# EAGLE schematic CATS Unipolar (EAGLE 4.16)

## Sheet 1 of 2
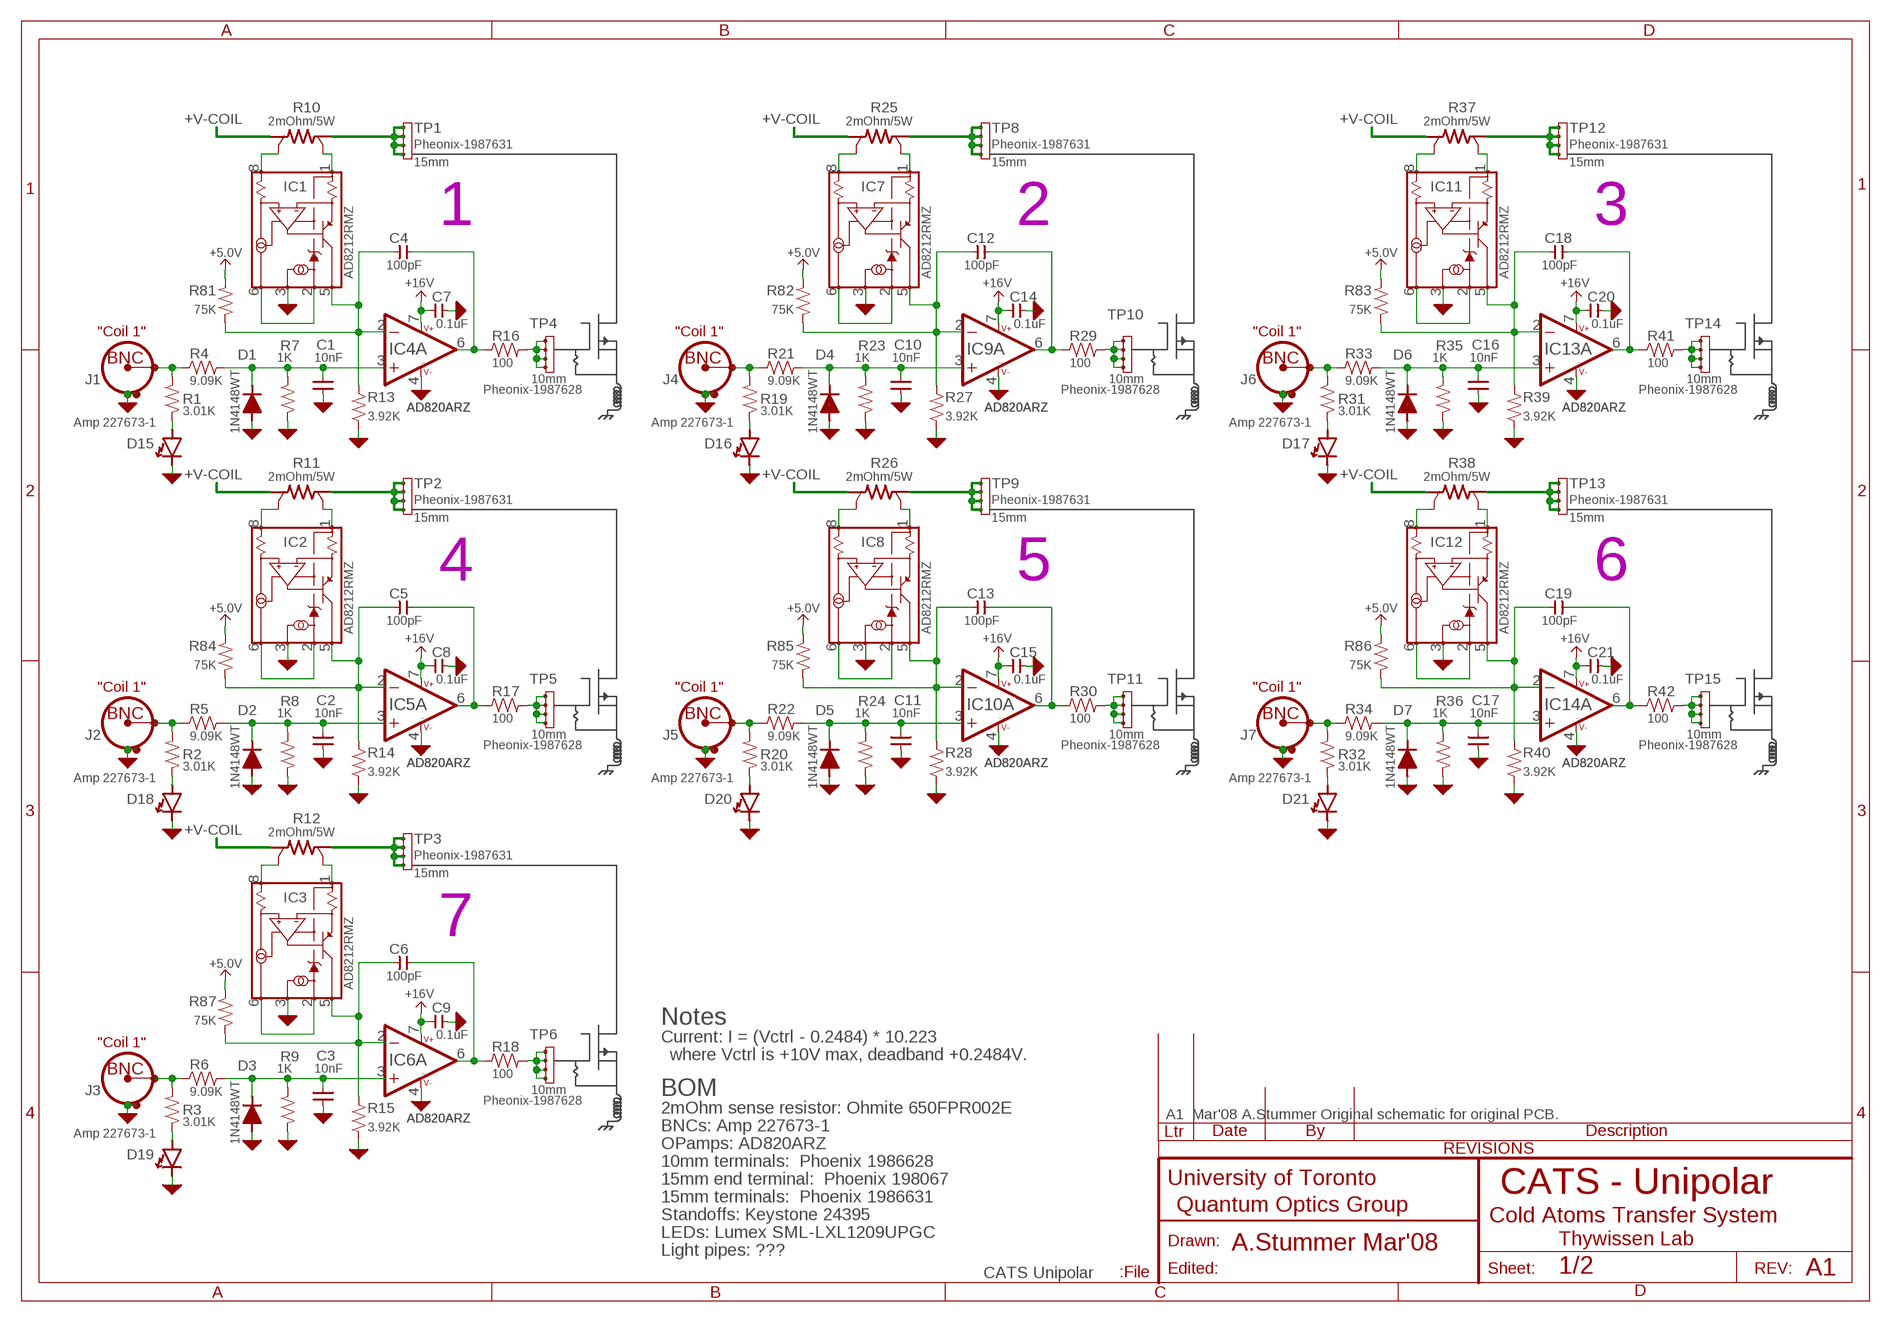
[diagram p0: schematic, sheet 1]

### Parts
C1  10nF  CAP-V-0805  [2012(0805)]
C2  10nF  CAP-V-0805  [2012(0805)]
C3  10nF  CAP-V-0805  [2012(0805)]
C4  100pF  CAP-H-0805  [2012(0805)]
C5  100pF  CAP-H-0805  [2012(0805)]
C6  100pF  CAP-H-0805  [2012(0805)]
C7  0.1uF  CAP-H-0805  [2012(0805)]
C8  0.1uF  CAP-H-0805  [2012(0805)]
C9  0.1uF  CAP-H-0805  [2012(0805)]
C10  10nF  CAP-V-0805  [2012(0805)]
C11  10nF  CAP-V-0805  [2012(0805)]
C12  100pF  CAP-H-0805  [2012(0805)]
C13  100pF  CAP-H-0805  [2012(0805)]
C14  0.1uF  CAP-H-0805  [2012(0805)]
C15  0.1uF  CAP-H-0805  [2012(0805)]
C16  10nF  CAP-V-0805  [2012(0805)]
C17  10nF  CAP-V-0805  [2012(0805)]
C18  100pF  CAP-H-0805  [2012(0805)]
C19  100pF  CAP-H-0805  [2012(0805)]
C20  0.1uF  CAP-H-0805  [2012(0805)]
C21  0.1uF  CAP-H-0805  [2012(0805)]
D1  1N4148WT  [SOD523]
D2  1N4148WT  [SOD523]
D3  1N4148WT  [SOD523]
D4  1N4148WT  [SOD523]
D5  1N4148WT  [SOD523]
D6  1N4148WT  [SOD523]
D7  1N4148WT  [SOD523]
D15  SML-LXL1209UPGC  LED-1209  [1209]
D16  SML-LXL1209UPGC  LED-1209  [1209]
D17  SML-LXL1209UPGC  LED-1209  [1209]
D18  SML-LXL1209UPGC  LED-1209  [1209]
D19  SML-LXL1209UPGC  LED-1209  [1209]
D20  SML-LXL1209UPGC  LED-1209  [1209]
D21  SML-LXL1209UPGC  LED-1209  [1209]
IC1  AD8212RMZ  AD8212(CURRENT_MONITOR)RMZ  [MSOP8]
IC2  AD8212RMZ  AD8212(CURRENT_MONITOR)RMZ  [MSOP8]
IC3  AD8212RMZ  AD8212(CURRENT_MONITOR)RMZ  [MSOP8]
IC4  AD820ARZ  OPAMP-SO8  [SOIC-8]
IC5  AD820ARZ  OPAMP-SO8  [SOIC-8]
IC6  AD820ARZ  OPAMP-SO8  [SOIC-8]
IC7  AD8212RMZ  AD8212(CURRENT_MONITOR)RMZ  [MSOP8]
IC8  AD8212RMZ  AD8212(CURRENT_MONITOR)RMZ  [MSOP8]
IC9  AD820ARZ  OPAMP-SO8  [SOIC-8]
IC10  AD820ARZ  OPAMP-SO8  [SOIC-8]
IC11  AD8212RMZ  AD8212(CURRENT_MONITOR)RMZ  [MSOP8]
IC12  AD8212RMZ  AD8212(CURRENT_MONITOR)RMZ  [MSOP8]
IC13  AD820ARZ  OPAMP-SO8  [SOIC-8]
IC14  AD820ARZ  OPAMP-SO8  [SOIC-8]
J1  Amp 227673-1  CONN-BNC-TYPE1VERT  [CONN-BNC-AMP-TYPE1VERT]
J2  Amp 227673-1  CONN-BNC-TYPE1VERT  [CONN-BNC-AMP-TYPE1VERT]
J3  Amp 227673-1  CONN-BNC-TYPE1VERT  [CONN-BNC-AMP-TYPE1VERT]
J4  Amp 227673-1  CONN-BNC-TYPE1VERT  [CONN-BNC-AMP-TYPE1VERT]
J5  Amp 227673-1  CONN-BNC-TYPE1VERT  [CONN-BNC-AMP-TYPE1VERT]
J6  Amp 227673-1  CONN-BNC-TYPE1VERT  [CONN-BNC-AMP-TYPE1VERT]
J7  Amp 227673-1  CONN-BNC-TYPE1VERT  [CONN-BNC-AMP-TYPE1VERT]
R1  3.01K  R-V-0805  [2012(0805)]
R2  3.01K  R-V-0805  [2012(0805)]
R3  3.01K  R-V-0805  [2012(0805)]
R4  9.09K  R-H-0805  [2012(0805)]
R5  9.09K  R-H-0805  [2012(0805)]
R6  9.09K  R-H-0805  [2012(0805)]
R7  1K  R-V-0805  [2012(0805)]
R8  1K  R-V-0805  [2012(0805)]
R9  1K  R-V-0805  [2012(0805)]
R10  2mOhm/5W  R-SENSE-OHMITE_650  [OHMITE_650]
R11  2mOhm/5W  R-SENSE-OHMITE_650  [OHMITE_650]
R12  2mOhm/5W  R-SENSE-OHMITE_650  [OHMITE_650]
R13  3.92K  R-V-0805  [2012(0805)]
R14  3.92K  R-V-0805  [2012(0805)]
R15  3.92K  R-V-0805  [2012(0805)]
R16  100  R-H-0805  [2012(0805)]
R17  100  R-H-0805  [2012(0805)]
R18  100  R-H-0805  [2012(0805)]
R19  3.01K  R-V-0805  [2012(0805)]
R20  3.01K  R-V-0805  [2012(0805)]
R21  9.09K  R-H-0805  [2012(0805)]
R22  9.09K  R-H-0805  [2012(0805)]
R23  1K  R-V-0805  [2012(0805)]
R24  1K  R-V-0805  [2012(0805)]
R25  2mOhm/5W  R-SENSE-OHMITE_650  [OHMITE_650]
R26  2mOhm/5W  R-SENSE-OHMITE_650  [OHMITE_650]
R27  3.92K  R-V-0805  [2012(0805)]
R28  3.92K  R-V-0805  [2012(0805)]
R29  100  R-H-0805  [2012(0805)]
R30  100  R-H-0805  [2012(0805)]
R31  3.01K  R-V-0805  [2012(0805)]
R32  3.01K  R-V-0805  [2012(0805)]
R33  9.09K  R-H-0805  [2012(0805)]
R34  9.09K  R-H-0805  [2012(0805)]
R35  1K  R-V-0805  [2012(0805)]
R36  1K  R-V-0805  [2012(0805)]
R37  2mOhm/5W  R-SENSE-OHMITE_650  [OHMITE_650]
R38  2mOhm/5W  R-SENSE-OHMITE_650  [OHMITE_650]
R39  3.92K  R-V-0805  [2012(0805)]
R40  3.92K  R-V-0805  [2012(0805)]
R41  100  R-H-0805  [2012(0805)]
R42  100  R-H-0805  [2012(0805)]
R81  75K  R-V-0805  [2012(0805)]
R82  75K  R-V-0805  [2012(0805)]
R83  75K  R-V-0805  [2012(0805)]
R84  75K  R-V-0805  [2012(0805)]
R85  75K  R-V-0805  [2012(0805)]
R86  75K  R-V-0805  [2012(0805)]
R87  75K  R-V-0805  [2012(0805)]
TP1  Pheonix-1987631  TP4-ZFKDS(10MM)  [PHEONIX_ZFKDS-10/15MM-TERMINAL-BLOCK]
TP2  Pheonix-1987631  TP4-ZFKDS(10MM)  [PHEONIX_ZFKDS-10/15MM-TERMINAL-BLOCK]
TP3  Pheonix-1987631  TP4-ZFKDS(10MM)  [PHEONIX_ZFKDS-10/15MM-TERMINAL-BLOCK]
TP4  Pheonix-1987628  TP4-ZFKDS(10MM)  [PHEONIX_ZFKDS-10/15MM-TERMINAL-BLOCK]
TP5  Pheonix-1987628  TP4-ZFKDS(10MM)  [PHEONIX_ZFKDS-10/15MM-TERMINAL-BLOCK]
TP6  Pheonix-1987628  TP4-ZFKDS(10MM)  [PHEONIX_ZFKDS-10/15MM-TERMINAL-BLOCK]
TP8  Pheonix-1987631  TP4-ZFKDS(10MM)  [PHEONIX_ZFKDS-10/15MM-TERMINAL-BLOCK]
TP9  Pheonix-1987631  TP4-ZFKDS(10MM)  [PHEONIX_ZFKDS-10/15MM-TERMINAL-BLOCK]
TP10  Pheonix-1987628  TP4-ZFKDS(10MM)  [PHEONIX_ZFKDS-10/15MM-TERMINAL-BLOCK]
TP11  Pheonix-1987628  TP4-ZFKDS(10MM)  [PHEONIX_ZFKDS-10/15MM-TERMINAL-BLOCK]
TP12  Pheonix-1987631  TP4-ZFKDS(10MM)  [PHEONIX_ZFKDS-10/15MM-TERMINAL-BLOCK]
TP13  Pheonix-1987631  TP4-ZFKDS(10MM)  [PHEONIX_ZFKDS-10/15MM-TERMINAL-BLOCK]
TP14  Pheonix-1987628  TP4-ZFKDS(10MM)  [PHEONIX_ZFKDS-10/15MM-TERMINAL-BLOCK]
TP15  Pheonix-1987628  TP4-ZFKDS(10MM)  [PHEONIX_ZFKDS-10/15MM-TERMINAL-BLOCK]

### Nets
+5.0V: R81.2 R82.2 R83.2 R84.2 R85.2 R86.2 R87.2 ; also sheet 2
+16V: C7.1 C8.1 C9.1 C14.1 C15.1 C20.1 C21.1 IC4.7(B:V+) IC5.7(B:V+) IC6.7(B:V+) IC9.7(B:V+) IC10.7(B:V+) IC13.7(B:V+) IC14.7(B:V+) ; also sheet 2
+V-COIL [Power]: R10.CURRENT1 R11.CURRENT1 R12.CURRENT1 R25.CURRENT1 R26.CURRENT1 R37.CURRENT1 R38.CURRENT1 ; also sheet 2
AGND: C1.1 C2.1 C3.1 C7.2 C8.2 C9.2 C10.1 C11.1 C14.2 C15.2 C16.1 C17.1 C20.2 C21.2 D1.A D2.A D3.A D4.A D5.A D6.A D7.A D15.K(C) D16.K(C) D17.K(C) D18.K(C) D19.K(C) D20.K(C) D21.K(C) IC1.3(BIAS) IC2.3(BIAS) IC3.3(BIAS) IC4.4(B:V-) IC5.4(B:V-) IC6.4(B:V-) IC7.3(BIAS) IC8.3(BIAS) IC9.4(B:V-) IC10.4(B:V-) IC11.3(BIAS) IC12.3(BIAS) IC13.4(B:V-) IC14.4(B:V-) J1.SHIELD1 J1.SHIELD2 J2.SHIELD1 J2.SHIELD2 J3.SHIELD1 J3.SHIELD2 J4.SHIELD1 J4.SHIELD2 J5.SHIELD1 J5.SHIELD2 J6.SHIELD1 J6.SHIELD2 J7.SHIELD1 J7.SHIELD2 R7.1 R8.1 R9.1 R13.1 R14.1 R15.1 R23.1 R24.1 R27.1 R28.1 R35.1 R36.1 R39.1 R40.1 ; also sheet 2
N$55: J3.CONDUCTOR R3.2 R6.1
N$56: C3.2 D3.C IC6.3(A:+IN) R6.2 R9.2
N$57: IC3.1(V+) R12.SENSE2
N$58: IC3.8(V-SENSE) R12.SENSE1
N$59: IC3.2(COM) IC3.6(ALPHA)
N$60: C6.1 IC3.5(I-OUT) IC6.2(A:-IN) R15.2 R87.1
N$61: C6.2 IC6.6(A:OUT) R18.1
N$62 [Power]: R12.CURRENT2 TP3.T@1(T) TP3.T@2(T) TP3.T@3(T) TP3.T@4(T)
N$63: R18.2 TP6.T@1(T) TP6.T@2(T) TP6.T@3(T) TP6.T@4(T)
N$64: J7.CONDUCTOR R32.2 R34.1
N$65: C17.2 D7.C IC14.3(A:+IN) R34.2 R36.2
N$66: IC12.1(V+) R38.SENSE2
N$67: IC12.8(V-SENSE) R38.SENSE1
N$68: IC12.2(COM) IC12.6(ALPHA)
N$69: C19.1 IC12.5(I-OUT) IC14.2(A:-IN) R40.2 R86.1
N$70: C19.2 IC14.6(A:OUT) R42.1
N$71 [Power]: R38.CURRENT2 TP13.T@1(T) TP13.T@2(T) TP13.T@3(T) TP13.T@4(T)
N$72: R42.2 TP15.T@1(T) TP15.T@2(T) TP15.T@3(T) TP15.T@4(T)
N$73: J5.CONDUCTOR R20.2 R22.1
N$74: C11.2 D5.C IC10.3(A:+IN) R22.2 R24.2
N$75: IC8.1(V+) R26.SENSE2
N$76: IC8.8(V-SENSE) R26.SENSE1
N$77: IC8.2(COM) IC8.6(ALPHA)
N$78: C13.1 IC8.5(I-OUT) IC10.2(A:-IN) R28.2 R85.1
N$79: C13.2 IC10.6(A:OUT) R30.1
N$80 [Power]: R26.CURRENT2 TP9.T@1(T) TP9.T@2(T) TP9.T@3(T) TP9.T@4(T)
N$81: R30.2 TP11.T@1(T) TP11.T@2(T) TP11.T@3(T) TP11.T@4(T)
N$82: J2.CONDUCTOR R2.2 R5.1
N$83: C2.2 D2.C IC5.3(A:+IN) R5.2 R8.2
N$84: IC2.1(V+) R11.SENSE2
N$85: IC2.8(V-SENSE) R11.SENSE1
N$86: IC2.2(COM) IC2.6(ALPHA)
N$87: C5.1 IC2.5(I-OUT) IC5.2(A:-IN) R14.2 R84.1
N$88: C5.2 IC5.6(A:OUT) R17.1
N$89 [Power]: R11.CURRENT2 TP2.T@1(T) TP2.T@2(T) TP2.T@3(T) TP2.T@4(T)
N$90: R17.2 TP5.T@1(T) TP5.T@2(T) TP5.T@3(T) TP5.T@4(T)
N$91: J6.CONDUCTOR R31.2 R33.1
N$92: C16.2 D6.C IC13.3(A:+IN) R33.2 R35.2
N$93: IC11.1(V+) R37.SENSE2
N$94: IC11.8(V-SENSE) R37.SENSE1
N$95: IC11.2(COM) IC11.6(ALPHA)
N$96: C18.1 IC11.5(I-OUT) IC13.2(A:-IN) R39.2 R83.1
N$97: C18.2 IC13.6(A:OUT) R41.1
N$98 [Power]: R37.CURRENT2 TP12.T@1(T) TP12.T@2(T) TP12.T@3(T) TP12.T@4(T)
N$99: R41.2 TP14.T@1(T) TP14.T@2(T) TP14.T@3(T) TP14.T@4(T)
N$100: J4.CONDUCTOR R19.2 R21.1
N$101: C10.2 D4.C IC9.3(A:+IN) R21.2 R23.2
N$102: IC7.1(V+) R25.SENSE2
N$103: IC7.8(V-SENSE) R25.SENSE1
N$104: IC7.2(COM) IC7.6(ALPHA)
N$105: C12.1 IC7.5(I-OUT) IC9.2(A:-IN) R27.2 R82.1
N$106: C12.2 IC9.6(A:OUT) R29.1
N$107 [Power]: R25.CURRENT2 TP8.T@1(T) TP8.T@2(T) TP8.T@3(T) TP8.T@4(T)
N$108: R29.2 TP10.T@1(T) TP10.T@2(T) TP10.T@3(T) TP10.T@4(T)
N$109: J1.CONDUCTOR R1.2 R4.1
N$110: C1.2 D1.C IC4.3(A:+IN) R4.2 R7.2
N$111: IC1.1(V+) R10.SENSE2
N$112: IC1.8(V-SENSE) R10.SENSE1
N$113: IC1.2(COM) IC1.6(ALPHA)
N$114: C4.1 IC1.5(I-OUT) IC4.2(A:-IN) R13.2 R81.1
N$115: C4.2 IC4.6(A:OUT) R16.1
N$116 [Power]: R10.CURRENT2 TP1.T@1(T) TP1.T@2(T) TP1.T@3(T) TP1.T@4(T)
N$117: R16.2 TP4.T@1(T) TP4.T@2(T) TP4.T@3(T) TP4.T@4(T)
N$131: D16.A R19.1
N$132: D17.A R31.1
N$133: D18.A R2.1
N$134: D20.A R20.1
N$135: D15.A R1.1
N$136: D21.A R32.1
N$137: D19.A R3.1

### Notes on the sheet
- 15mm | 15mm | 15mm
- 1 | 2 | 3
- "Coil 1" | "Coil 1" | "Coil 1"
- 10mm | 10mm | 10mm
- 15mm | 15mm | 15mm
- 4 | 5 | 6
- "Coil 1" | "Coil 1" | "Coil 1"
- 10mm | 10mm | 10mm
- 15mm
- 7
- Notes
- Current: I = (Vctrl - 0.2484) * 10.223
- "Coil 1"
- where Vctrl is +10V max, deadband +0.2484V.
- 10mm | BOM
- 2mOhm sense resistor: Ohmite 650FPR002E
- A1  Mar'08 A.Stummer Original schematic for original PCB.
- BNCs: Amp 227673-1
- OPamps: AD820ARZ
- 10mm terminals:  Phoenix 1986628
- 15mm end terminal:  Phoenix 198067
- CATS - Unipolar
- 15mm terminals:  Phoenix 1986631
- Standoffs: Keystone 24395 | Cold Atoms Transfer System
- LEDs: Lumex SML-LXL1209UPGC
- A.Stummer Mar'08 | Thywissen Lab
- Light pipes: ???
- A1

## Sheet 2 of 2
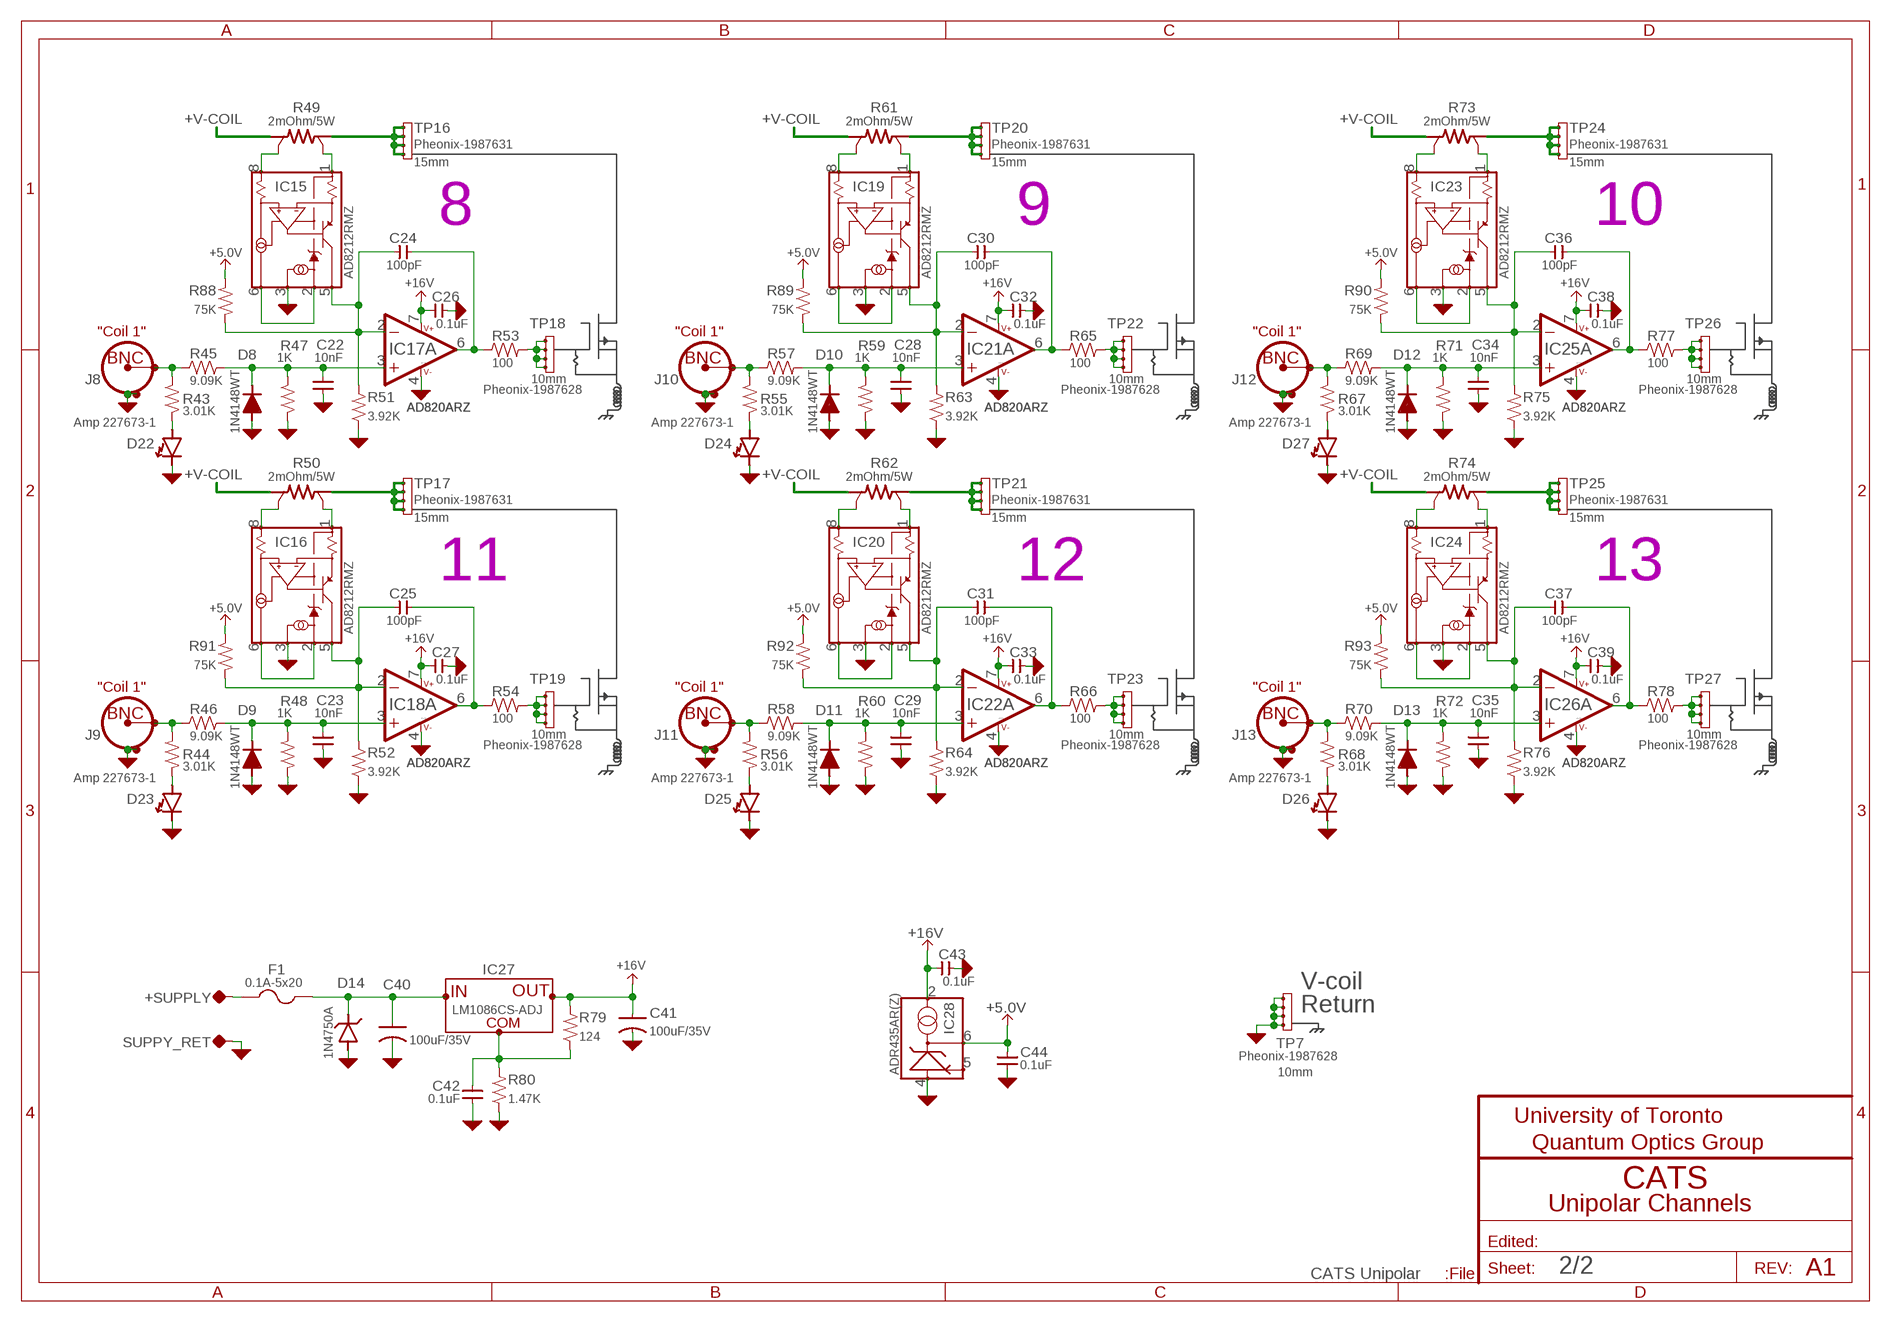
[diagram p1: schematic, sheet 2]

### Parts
+SUPPLY  TP-0.042B  [TP-0.042B]
C22  10nF  CAP-V-0805  [2012(0805)]
C23  10nF  CAP-V-0805  [2012(0805)]
C24  100pF  CAP-H-0805  [2012(0805)]
C25  100pF  CAP-H-0805  [2012(0805)]
C26  0.1uF  CAP-H-0805  [2012(0805)]
C27  0.1uF  CAP-H-0805  [2012(0805)]
C28  10nF  CAP-V-0805  [2012(0805)]
C29  10nF  CAP-V-0805  [2012(0805)]
C30  100pF  CAP-H-0805  [2012(0805)]
C31  100pF  CAP-H-0805  [2012(0805)]
C32  0.1uF  CAP-H-0805  [2012(0805)]
C33  0.1uF  CAP-H-0805  [2012(0805)]
C34  10nF  CAP-V-0805  [2012(0805)]
C35  10nF  CAP-V-0805  [2012(0805)]
C36  100pF  CAP-H-0805  [2012(0805)]
C37  100pF  CAP-H-0805  [2012(0805)]
C38  0.1uF  CAP-H-0805  [2012(0805)]
C39  0.1uF  CAP-H-0805  [2012(0805)]
C40  100uF/35V  CAP-POL-EIA-A  [EIA-A]
C41  100uF/35V  CAP-POL-EIA-A  [EIA-A]
C42  0.1uF  CAP-V-0805  [2012(0805)]
C43  0.1uF  CAP-H-0805  [2012(0805)]
C44  0.1uF  CAP-V-0805  [2012(0805)]
D8  1N4148WT  [SOD523]
D9  1N4148WT  [SOD523]
D10  1N4148WT  [SOD523]
D11  1N4148WT  [SOD523]
D12  1N4148WT  [SOD523]
D13  1N4148WT  [SOD523]
D14  1N4750A  ZENER-THROUGH-0.4"  [PASSIVE_0.4"]
D22  SML-LXL1209UPGC  LED-1209  [1209]
D23  SML-LXL1209UPGC  LED-1209  [1209]
D24  SML-LXL1209UPGC  LED-1209  [1209]
D25  SML-LXL1209UPGC  LED-1209  [1209]
D26  SML-LXL1209UPGC  LED-1209  [1209]
D27  SML-LXL1209UPGC  LED-1209  [1209]
F1  0.1A-5x20  FUSE-5X20-4  [FUSE]
IC15  AD8212RMZ  AD8212(CURRENT_MONITOR)RMZ  [MSOP8]
IC16  AD8212RMZ  AD8212(CURRENT_MONITOR)RMZ  [MSOP8]
IC17  AD820ARZ  OPAMP-SO8  [SOIC-8]
IC18  AD820ARZ  OPAMP-SO8  [SOIC-8]
IC19  AD8212RMZ  AD8212(CURRENT_MONITOR)RMZ  [MSOP8]
IC20  AD8212RMZ  AD8212(CURRENT_MONITOR)RMZ  [MSOP8]
IC21  AD820ARZ  OPAMP-SO8  [SOIC-8]
IC22  AD820ARZ  OPAMP-SO8  [SOIC-8]
IC23  AD8212RMZ  AD8212(CURRENT_MONITOR)RMZ  [MSOP8]
IC24  AD8212RMZ  AD8212(CURRENT_MONITOR)RMZ  [MSOP8]
IC25  AD820ARZ  OPAMP-SO8  [SOIC-8]
IC26  AD820ARZ  OPAMP-SO8  [SOIC-8]
IC27  LM1086CS-ADJ  LM1086-TO263  [TO263]
IC28  ADR435AR(Z)  ADR43_(REFERENCE)-SOIC8  [SOIC-8]
J8  Amp 227673-1  CONN-BNC-TYPE1VERT  [CONN-BNC-AMP-TYPE1VERT]
J9  Amp 227673-1  CONN-BNC-TYPE1VERT  [CONN-BNC-AMP-TYPE1VERT]
J10  Amp 227673-1  CONN-BNC-TYPE1VERT  [CONN-BNC-AMP-TYPE1VERT]
J11  Amp 227673-1  CONN-BNC-TYPE1VERT  [CONN-BNC-AMP-TYPE1VERT]
J12  Amp 227673-1  CONN-BNC-TYPE1VERT  [CONN-BNC-AMP-TYPE1VERT]
J13  Amp 227673-1  CONN-BNC-TYPE1VERT  [CONN-BNC-AMP-TYPE1VERT]
R43  3.01K  R-V-0805  [2012(0805)]
R44  3.01K  R-V-0805  [2012(0805)]
R45  9.09K  R-H-0805  [2012(0805)]
R46  9.09K  R-H-0805  [2012(0805)]
R47  1K  R-V-0805  [2012(0805)]
R48  1K  R-V-0805  [2012(0805)]
R49  2mOhm/5W  R-SENSE-OHMITE_650  [OHMITE_650]
R50  2mOhm/5W  R-SENSE-OHMITE_650  [OHMITE_650]
R51  3.92K  R-V-0805  [2012(0805)]
R52  3.92K  R-V-0805  [2012(0805)]
R53  100  R-H-0805  [2012(0805)]
R54  100  R-H-0805  [2012(0805)]
R55  3.01K  R-V-0805  [2012(0805)]
R56  3.01K  R-V-0805  [2012(0805)]
R57  9.09K  R-H-0805  [2012(0805)]
R58  9.09K  R-H-0805  [2012(0805)]
R59  1K  R-V-0805  [2012(0805)]
R60  1K  R-V-0805  [2012(0805)]
R61  2mOhm/5W  R-SENSE-OHMITE_650  [OHMITE_650]
R62  2mOhm/5W  R-SENSE-OHMITE_650  [OHMITE_650]
R63  3.92K  R-V-0805  [2012(0805)]
R64  3.92K  R-V-0805  [2012(0805)]
R65  100  R-H-0805  [2012(0805)]
R66  100  R-H-0805  [2012(0805)]
R67  3.01K  R-V-0805  [2012(0805)]
R68  3.01K  R-V-0805  [2012(0805)]
R69  9.09K  R-H-0805  [2012(0805)]
R70  9.09K  R-H-0805  [2012(0805)]
R71  1K  R-V-0805  [2012(0805)]
R72  1K  R-V-0805  [2012(0805)]
R73  2mOhm/5W  R-SENSE-OHMITE_650  [OHMITE_650]
R74  2mOhm/5W  R-SENSE-OHMITE_650  [OHMITE_650]
R75  3.92K  R-V-0805  [2012(0805)]
R76  3.92K  R-V-0805  [2012(0805)]
R77  100  R-H-0805  [2012(0805)]
R78  100  R-H-0805  [2012(0805)]
R79  124  R-V-0805  [2012(0805)]
R80  1.47K  R-V-0805  [2012(0805)]
R88  75K  R-V-0805  [2012(0805)]
R89  75K  R-V-0805  [2012(0805)]
R90  75K  R-V-0805  [2012(0805)]
R91  75K  R-V-0805  [2012(0805)]
R92  75K  R-V-0805  [2012(0805)]
R93  75K  R-V-0805  [2012(0805)]
SUPPY_RET  TP-0.042B  [TP-0.042B]
TP7  Pheonix-1987628  TP4-ZFKDS(10MM)  [PHEONIX_ZFKDS-10/15MM-TERMINAL-BLOCK]
TP16  Pheonix-1987631  TP4-ZFKDS(10MM)  [PHEONIX_ZFKDS-10/15MM-TERMINAL-BLOCK]
TP17  Pheonix-1987631  TP4-ZFKDS(10MM)  [PHEONIX_ZFKDS-10/15MM-TERMINAL-BLOCK]
TP18  Pheonix-1987628  TP4-ZFKDS(10MM)  [PHEONIX_ZFKDS-10/15MM-TERMINAL-BLOCK]
TP19  Pheonix-1987628  TP4-ZFKDS(10MM)  [PHEONIX_ZFKDS-10/15MM-TERMINAL-BLOCK]
TP20  Pheonix-1987631  TP4-ZFKDS(10MM)  [PHEONIX_ZFKDS-10/15MM-TERMINAL-BLOCK]
TP21  Pheonix-1987631  TP4-ZFKDS(10MM)  [PHEONIX_ZFKDS-10/15MM-TERMINAL-BLOCK]
TP22  Pheonix-1987628  TP4-ZFKDS(10MM)  [PHEONIX_ZFKDS-10/15MM-TERMINAL-BLOCK]
TP23  Pheonix-1987628  TP4-ZFKDS(10MM)  [PHEONIX_ZFKDS-10/15MM-TERMINAL-BLOCK]
TP24  Pheonix-1987631  TP4-ZFKDS(10MM)  [PHEONIX_ZFKDS-10/15MM-TERMINAL-BLOCK]
TP25  Pheonix-1987631  TP4-ZFKDS(10MM)  [PHEONIX_ZFKDS-10/15MM-TERMINAL-BLOCK]
TP26  Pheonix-1987628  TP4-ZFKDS(10MM)  [PHEONIX_ZFKDS-10/15MM-TERMINAL-BLOCK]
TP27  Pheonix-1987628  TP4-ZFKDS(10MM)  [PHEONIX_ZFKDS-10/15MM-TERMINAL-BLOCK]

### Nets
+5.0V: C44.2 IC28.6(OUT) R88.2 R89.2 R90.2 R91.2 R92.2 R93.2 ; also sheet 1
+16V: C26.1 C27.1 C32.1 C33.1 C38.1 C39.1 C41.2(POS) C43.1 IC17.7(B:V+) IC18.7(B:V+) IC21.7(B:V+) IC22.7(B:V+) IC25.7(B:V+) IC26.7(B:V+) IC27.2(OUT) IC28.2(VIN) R79.2 ; also sheet 1
+V-COIL [Power]: R49.CURRENT1 R50.CURRENT1 R61.CURRENT1 R62.CURRENT1 R73.CURRENT1 R74.CURRENT1 ; also sheet 1
AGND: C22.1 C23.1 C26.2 C27.2 C28.1 C29.1 C32.2 C33.2 C34.1 C35.1 C38.2 C39.2 C40.1(NEG) C41.1(NEG) C42.1 C43.2 C44.1 D8.A D9.A D10.A D11.A D12.A D13.A D14.1(A) D22.K(C) D23.K(C) D24.K(C) D25.K(C) D26.K(C) D27.K(C) IC15.3(BIAS) IC16.3(BIAS) IC17.4(B:V-) IC18.4(B:V-) IC19.3(BIAS) IC20.3(BIAS) IC21.4(B:V-) IC22.4(B:V-) IC23.3(BIAS) IC24.3(BIAS) IC25.4(B:V-) IC26.4(B:V-) IC28.4(COM) J8.SHIELD1 J8.SHIELD2 J9.SHIELD1 J9.SHIELD2 J10.SHIELD1 J10.SHIELD2 J11.SHIELD1 J11.SHIELD2 J12.SHIELD1 J12.SHIELD2 J13.SHIELD1 J13.SHIELD2 R47.1 R48.1 R51.1 R52.1 R59.1 R60.1 R63.1 R64.1 R71.1 R72.1 R75.1 R76.1 R80.1 SUPPY_RET.TP TP7.T@1(T) TP7.T@2(T) TP7.T@3(T) TP7.T@4(T) ; also sheet 1
N$1: J13.CONDUCTOR R68.2 R70.1
N$2: C35.2 D13.C IC26.3(A:+IN) R70.2 R72.2
N$3: IC24.1(V+) R74.SENSE2
N$4: IC24.8(V-SENSE) R74.SENSE1
N$5: IC24.2(COM) IC24.6(ALPHA)
N$6: C37.1 IC24.5(I-OUT) IC26.2(A:-IN) R76.2 R93.1
N$7: C37.2 IC26.6(A:OUT) R78.1
N$8 [Power]: R74.CURRENT2 TP25.T@1(T) TP25.T@2(T) TP25.T@3(T) TP25.T@4(T)
N$9: J11.CONDUCTOR R56.2 R58.1
N$10: R78.2 TP27.T@1(T) TP27.T@2(T) TP27.T@3(T) TP27.T@4(T)
N$11: C29.2 D11.C IC22.3(A:+IN) R58.2 R60.2
N$12: IC20.1(V+) R62.SENSE2
N$13: IC20.8(V-SENSE) R62.SENSE1
N$14: IC20.2(COM) IC20.6(ALPHA)
N$15: C31.1 IC20.5(I-OUT) IC22.2(A:-IN) R64.2 R92.1
N$16: C31.2 IC22.6(A:OUT) R66.1
N$17 [Power]: R62.CURRENT2 TP21.T@1(T) TP21.T@2(T) TP21.T@3(T) TP21.T@4(T)
N$18: R66.2 TP23.T@1(T) TP23.T@2(T) TP23.T@3(T) TP23.T@4(T)
N$19: J9.CONDUCTOR R44.2 R46.1
N$20: C23.2 D9.C IC18.3(A:+IN) R46.2 R48.2
N$21: IC16.1(V+) R50.SENSE2
N$22: IC16.8(V-SENSE) R50.SENSE1
N$23: IC16.2(COM) IC16.6(ALPHA)
N$24: C25.1 IC16.5(I-OUT) IC18.2(A:-IN) R52.2 R91.1
N$25: C25.2 IC18.6(A:OUT) R54.1
N$26 [Power]: R50.CURRENT2 TP17.T@1(T) TP17.T@2(T) TP17.T@3(T) TP17.T@4(T)
N$27: R54.2 TP19.T@1(T) TP19.T@2(T) TP19.T@3(T) TP19.T@4(T)
N$28: J12.CONDUCTOR R67.2 R69.1
N$29: C34.2 D12.C IC25.3(A:+IN) R69.2 R71.2
N$30: IC23.1(V+) R73.SENSE2
N$31: IC23.8(V-SENSE) R73.SENSE1
N$32: IC23.2(COM) IC23.6(ALPHA)
N$33: C36.1 IC23.5(I-OUT) IC25.2(A:-IN) R75.2 R90.1
N$34: C36.2 IC25.6(A:OUT) R77.1
N$35 [Power]: R73.CURRENT2 TP24.T@1(T) TP24.T@2(T) TP24.T@3(T) TP24.T@4(T)
N$36: R77.2 TP26.T@1(T) TP26.T@2(T) TP26.T@3(T) TP26.T@4(T)
N$37: J10.CONDUCTOR R55.2 R57.1
N$38: C28.2 D10.C IC21.3(A:+IN) R57.2 R59.2
N$39: IC19.1(V+) R61.SENSE2
N$40: IC19.8(V-SENSE) R61.SENSE1
N$41: IC19.2(COM) IC19.6(ALPHA)
N$42: C30.1 IC19.5(I-OUT) IC21.2(A:-IN) R63.2 R89.1
N$43: C30.2 IC21.6(A:OUT) R65.1
N$44 [Power]: R61.CURRENT2 TP20.T@1(T) TP20.T@2(T) TP20.T@3(T) TP20.T@4(T)
N$45: R65.2 TP22.T@1(T) TP22.T@2(T) TP22.T@3(T) TP22.T@4(T)
N$46: J8.CONDUCTOR R43.2 R45.1
N$47: C22.2 D8.C IC17.3(A:+IN) R45.2 R47.2
N$48: IC15.1(V+) R49.SENSE2
N$49: IC15.8(V-SENSE) R49.SENSE1
N$50: IC15.2(COM) IC15.6(ALPHA)
N$51: C24.1 IC15.5(I-OUT) IC17.2(A:-IN) R51.2 R88.1
N$52: C24.2 IC17.6(A:OUT) R53.1
N$53 [Power]: R49.CURRENT2 TP16.T@1(T) TP16.T@2(T) TP16.T@3(T) TP16.T@4(T)
N$54: R53.2 TP18.T@1(T) TP18.T@2(T) TP18.T@3(T) TP18.T@4(T)
N$138: D22.A R43.1
N$139: D23.A R44.1
N$140: D25.A R56.1
N$141: D24.A R55.1
N$142: D27.A R67.1
N$143: D26.A R68.1
N$144: +SUPPLY.TP F1.1A
N$145: C40.2(POS) D14.2(C) F1.2A IC27.3(VI)
N$146: C42.2 IC27.1(COM) R79.1 R80.2
Unconnected: IC28.5(TRIM)

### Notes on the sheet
- 15mm | 15mm | 15mm
- 8 | 9 | 10
- "Coil 1" | "Coil 1" | "Coil 1"
- 10mm | 10mm | 10mm
- 15mm | 15mm | 15mm
- 11 | 12 | 13
- "Coil 1" | "Coil 1" | "Coil 1"
- 10mm | 10mm | 10mm
- V-coil
- Return
- 10mm
- CATS
- Unipolar Channels
- A1

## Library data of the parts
+SUPPLY SUPPY_RET = QuantumOptics:TP: Testpoint, test point on schematic, on PCB either SMT pad, small hole or loop style TP.
C1-C3 C10 C11 C16 C17 C22 C23 C28 C29 C34 C35 C42 C44 = QuantumOptics:CAP-V-: Cap, SMT and Through-hole, 0402 and up.
C4-C9 C12-C15 C18-C21 C24-C27 C30-C33 C36-C39 C43 = QuantumOptics:CAP-H-: Cap, SMT and Through-hole, 0402 and up.
C40 C41 = QuantumOptics:CAP-POL-: Capacitor, Polarized, SMT 0805 and up, probably tantalum.
D1-D13 = QuantumOptics:1N4148: 1N4148, fast small signal silicon, 80V 125mAavg trr=4nSmax
D14 = QuantumOptics:ZENER: Zener
D15-D27 = QuantumOptics:LED: LED
F1 = QuantumOptics:FUSE: Fuse
IC1-IC3 IC7 IC8 IC11 IC12 IC15 IC16 IC19 IC20 IC23 IC24 = QuantumOptics:AD8212(CURRENT_MONITOR): AD8212 Current Sense Monitor, Analog Devices, 7-65V, current output. http://www.analog.com/UploadedFiles/Data_Sheets/AD8212.pdf
IC4-IC6 IC9 IC10 IC13 IC14 IC17 IC18 IC21 IC22 IC25 IC26 = QuantumOptics:OPAMP: Op Amp, generic, pick the right package. e.g. AD8605: SOT-23-5, RRIO, 10MHz, Ib = 1pA, Vio < 65uV, 2.7-5.5V.
IC27 = QuantumOptics:LM1086: LM1086-xxx, National Semiconductor, LDO, adjustable or fixed. http://cache.national.com/ds/LM/LM1086.pdf
IC28 = QuantumOptics:ADR43_(REFERENCE): ADR43x Reference, regulator style with trim, 2V to 5V, sink or source, 3-10PPM/°. http://www.analog.com/UploadedFiles/Data_Sheets/ADR430_431_433_434_435_439.pdf
J1-J13 = QuantumOptics:CONN-BNC: BNC PCB, horizontal, Amp 227677-1, nut 1-329631-2, shoulder washer 330620. The two shield connections allow the assembly on either side of the board. http://catalog.tycoelectronics.com/TE/bin/TE.Connect?C=1&PN=227677-1&M=STARTSWITH&LG=1&I=13&button.x=0&button.y=0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
R1-R3 R7-R9 R13-R15 R19 R20 R23 R24 R27 R28 R31 R32 R35 R36 R39 R40 R43 R44 R47 R48 R51 R52 R55 R56 R59 R60 R63 R64 R67 R68 R71 R72 R75 R76 R79-R93 = QuantumOptics:R-V-*: Resistor, SMT & Through-Hole, vertical symbol
R4-R6 R16-R18 R21 R22 R29 R30 R33 R34 R41 R42 R45 R46 R53 R54 R57 R58 R65 R66 R69 R70 R77 R78 = QuantumOptics:R-H-*: Resistor, SMT & Through-Hole, horizontal symbol
R10-R12 R25 R26 R37 R38 R49 R50 R61 R62 R73 R74 = QuantumOptics:R-SENSE: Current sense resistor, 4-terminal. e.g. Ohmite series 60, http://www.ohmite.com/cgi-bin/showpage.cgi?product=60-4_series
TP1-TP27 = QuantumOptics:TP4: Terminal block or connection with 4 holes, based on Pheonix 1987054.

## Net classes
0 default: clearance 0.406 mm
1 Power: width 1.27 mm, drill 0.178 mm, clearance 3.175 mm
